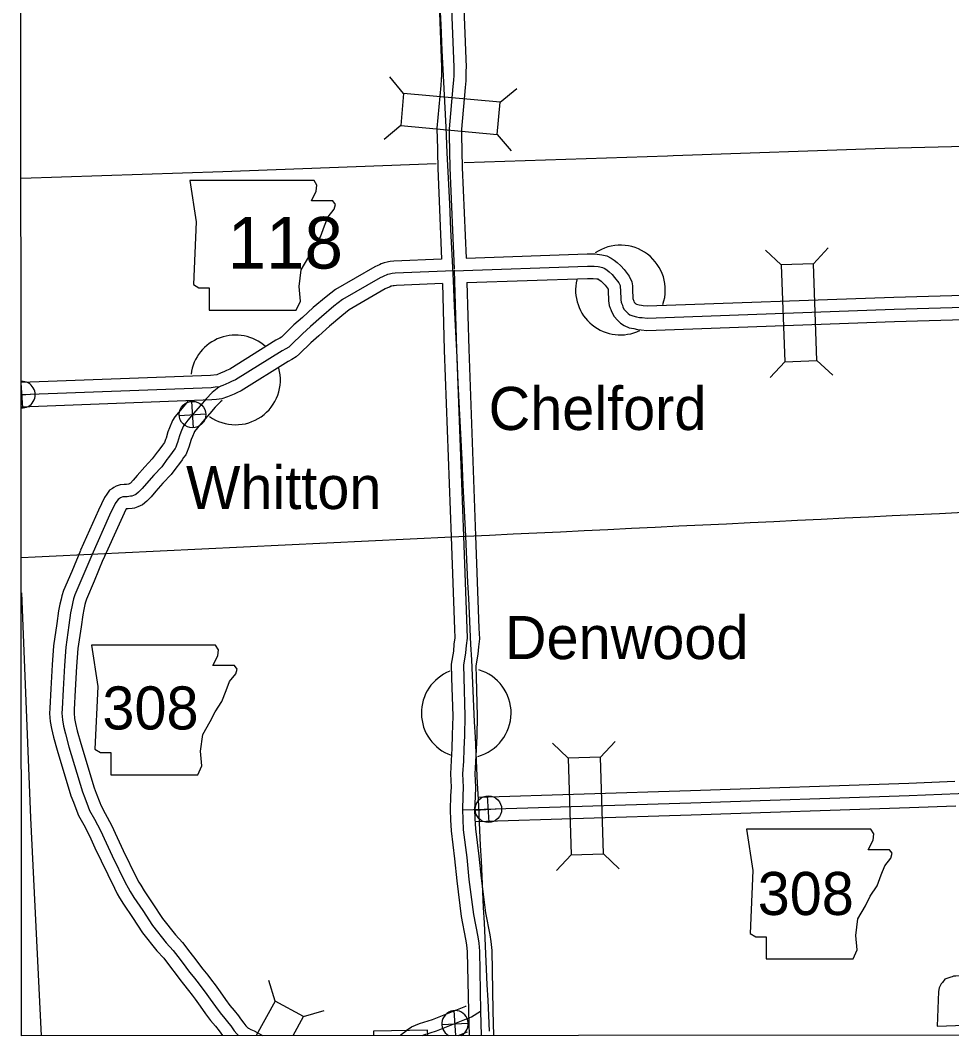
# Model space of a CAD drawing. Extents: x 2520745 to 2582119, y -1491628 to -1461664.
# Drawn here: x 2520745 to 2524549, y -1472053 to -1467904 of the extents above; entities that cross this region are included whole.
import ezdxf

# ---------------------------------------------------------------- set-up
doc = ezdxf.new("R2010")
doc.units = 0
for name, color, linetype in [('1', 7, 'Continuous'), ('10', 7, 'Continuous'), ('2', 7, 'Continuous'), ('20', 7, 'Continuous'), ('21', 7, 'Continuous'), ('24', 7, 'Continuous'), ('26', 7, 'Continuous'), ('4', 7, 'Continuous'), ('59', 7, 'Continuous'), ('6', 7, 'Continuous'), ('60', 7, 'Continuous')]:
    doc.layers.add(name, color=color, linetype=linetype)

msp = doc.modelspace()

# ---------------------------------------------------------------- linework, layer by layer
at = {"layer": '1'}
msp.add_lwpolyline([(2520744.9, -1463342.8), (2532121.5, -1463335.8), (2532126.8, -1472046.5), (2520750.2, -1472053.4)], close=True, dxfattribs=at)
at = {"layer": '10'}
for points in [[(2522449.7, -1467687), (2522465.2, -1468096.3), (2522464.9, -1468109.6), (2522465, -1468128.3), (2522464.3, -1468145.7), (2522462.1, -1468170), (2522446.4, -1468344.5), (2522446.2, -1468353.9), (2522446.5, -1468360.6), (2522447.2, -1468375.4), (2522449.9, -1468508.5), (2522465.4, -1468880.1)], [(2522549.6, -1467682.6), (2522565.3, -1468095.8), (2522564.9, -1468110.6), (2522565, -1468130), (2522564.1, -1468152.2), (2522561.8, -1468178.9), (2522546.3, -1468349.7), (2522546.3, -1468352.4), (2522546.4, -1468356.4), (2522547.1, -1468372.3), (2522549.8, -1468505.4), (2522565.4, -1468876.4)], [(2522565.4, -1468876.4), (2523060.1, -1468858.7), (2523091.7, -1468858.9), (2523110.4, -1468861.2), (2523119.5, -1468862.1), (2523140.4, -1468866.4), (2523157.7, -1468876.1), (2523170.7, -1468884.7), (2523182.7, -1468894.1), (2523197.7, -1468908.2), (2523210.6, -1468923), (2523231.5, -1468949.7), (2523242.9, -1468972.3), (2523245.3, -1468989.9), (2523245.9, -1469004.7), (2523246.9, -1469041.5), (2523251, -1469051.6), (2523252.7, -1469056.9), (2523254.8, -1469059.1), (2523259.3, -1469063.4), (2523261.4, -1469064.3), (2523273, -1469066.7), (2523281.4, -1469068.9), (2523288.3, -1469069.2), (2523306.8, -1469071.1), (2524312.7, -1469035.1), (2524973.8, -1469016.2)], [(2522465.4, -1468880.1), (2522270.9, -1468887.8), (2522255.9, -1468890.1), (2522248.7, -1468891.3), (2522242.9, -1468892.6), (2522230.4, -1468894.8), (2522219.4, -1468899.5), (2522211.3, -1468903.2), (2522205.2, -1468906), (2522192.4, -1468911), (2522032, -1469003.9), (2521994.2, -1469034), (2521941.6, -1469078.2), (2521897.3, -1469118.5), (2521862.7, -1469149.1), (2521816.1, -1469194.7), (2521811.3, -1469199.3), (2521805.5, -1469202.7), (2521789, -1469211.5), (2521600.5, -1469329.3), (2521586.4, -1469335.5), (2521576.2, -1469340.5), (2521564.7, -1469345.4), (2521547.3, -1469353.2)], [(2522568.7, -1468976.3), (2523061.6, -1468958.7), (2523085.3, -1468958.9), (2523099.4, -1468960.6), (2523104.4, -1468961.1), (2523105, -1468961.2), (2523105.5, -1468961.5), (2523112.4, -1468966), (2523117.5, -1468970.1), (2523125.5, -1468977.7), (2523133.6, -1468986.8), (2523145.8, -1469002.4), (2523146, -1469008.1), (2523147.1, -1469050.5), (2523150, -1469069.7), (2523154.6, -1469080.1), (2523156.9, -1469085.7), (2523159.8, -1469094.8), (2523170.1, -1469115.2), (2523184, -1469129.8), (2523195.9, -1469141.2), (2523210.9, -1469151.6), (2523232.2, -1469160.3), (2523250.2, -1469164.1), (2523266.1, -1469168.2), (2523280.6, -1469169), (2523303.5, -1469171.3), (2524315.9, -1469135.1), (2524976.7, -1469116.1)], [(2522468.8, -1468980.1), (2522280.7, -1468987.5), (2522271.9, -1468988.9), (2522267.9, -1468989.5), (2522262.4, -1468990.7), (2522259.1, -1468991.3), (2522252.8, -1468994.2), (2522244.4, -1468998), (2522235.7, -1469001.4), (2522088.5, -1469086.7), (2522057.5, -1469111.4), (2522007.4, -1469153.5), (2521964.1, -1469192.9), (2521930.8, -1469222.3), (2521885.6, -1469266.7), (2521871.9, -1469279.6), (2521854.3, -1469290), (2521839, -1469298.2), (2521647.2, -1469418.1), (2521628.6, -1469426.2), (2521618, -1469431.4), (2521604.7, -1469437), (2521590.8, -1469443.3), (2521567.3, -1469451.5)], [(2522468.8, -1468980.1), (2522476.3, -1469251.3)], [(2522568.7, -1468976.3), (2522576.3, -1469248.6)], [(2522476.3, -1469251.8), (2522504.4, -1470014.6), (2522518.2, -1470391.8), (2522519.6, -1470427.2), (2522516.2, -1470454), (2522513.9, -1470482.1), (2522504.9, -1470535.4), (2522506.4, -1470590.8), (2522510.9, -1470747.5), (2522509, -1470824.5), (2522506.8, -1470879.8), (2522504.5, -1470928.6), (2522501.5, -1470982.8), (2522504, -1471038), (2522502.2, -1471072.9), (2522500.2, -1471130.6), (2522501.8, -1471171.4), (2522504.5, -1471216.5), (2522518.6, -1471331.2), (2522527.4, -1471420.4), (2522546, -1471566.4), (2522563.7, -1471658.6), (2522567.5, -1471681.5), (2522570.2, -1471710.3), (2522574.9, -1471953.7)], [(2522576.2, -1469248.1), (2522604.4, -1470010.9), (2522618.2, -1470388), (2522619.8, -1470431.5), (2522615.7, -1470464.3), (2522613.2, -1470494.5), (2522605.1, -1470542.5), (2522606.3, -1470588), (2522611, -1470747.4), (2522608.9, -1470827.7), (2522606.7, -1470884.1), (2522604.4, -1470933.7), (2522601.6, -1470983.3), (2522604.1, -1471038.3), (2522602.1, -1471077.1), (2522600.3, -1471130.4), (2522601.7, -1471166.5), (2522604.1, -1471207.5), (2522618, -1471320.2), (2522626.8, -1471409.2), (2522644.8, -1471550.7), (2522662.2, -1471641), (2522666.7, -1471668.7), (2522670.1, -1471704.7), (2522674.9, -1471951.8)], [(2521547.3, -1469353.2), (2521521.3, -1469355.5), (2520748.6, -1469384.4)], [(2521567.3, -1469451.5), (2521545.7, -1469453.7), (2521527.5, -1469455.3), (2520748.6, -1469484.4)], [(2521569.2, -1469457.4), (2521562, -1469463), (2521540.7, -1469484.7), (2521518.8, -1469511.1), (2521488.7, -1469545.4), (2521468.3, -1469569.8), (2521456.5, -1469584.8), (2521454.3, -1469587.9), (2521447.5, -1469604.6), (2521443, -1469617.3), (2521433.8, -1469648.2), (2521430.1, -1469655.9), (2521426.7, -1469665.7), (2521420.7, -1469680.2), (2521411.8, -1469691.3), (2521405.5, -1469699.6), (2521390.3, -1469720.9), (2521383.9, -1469729), (2521361.2, -1469760.4), (2521327, -1469796.2), (2521298.8, -1469828.9), (2521279.7, -1469851.5), (2521261.8, -1469869.5), (2521244.4, -1469883.6), (2521225.5, -1469893), (2521211.9, -1469897.2), (2521201.1, -1469898.9), (2521184.8, -1469900.9), (2521177.8, -1469901), (2521176.3, -1469903.4), (2521154.9, -1469947.6), (2521082.1, -1470110.6)], [(2521429.7, -1469461.1), (2521412.7, -1469480.4), (2521390.7, -1469506.8), (2521376.1, -1469525.1), (2521365.8, -1469540), (2521354, -1469569), (2521347.9, -1469586.3), (2521340.4, -1469611.7), (2521337.4, -1469617.7), (2521333.6, -1469629), (2521333.2, -1469629.5), (2521325.1, -1469640), (2521310.2, -1469660.9), (2521304.1, -1469668.7), (2521284.1, -1469696.2), (2521252.9, -1469729), (2521222.8, -1469763.9), (2521206, -1469783.8), (2521194.6, -1469795.3), (2521190, -1469798.9), (2521188.6, -1469799.6), (2521187.4, -1469799.8), (2521178, -1469801), (2521168.9, -1469801.1), (2521153.3, -1469802.5), (2521136.9, -1469807.6), (2521126.9, -1469813.3), (2521121.9, -1469816.8), (2521109.8, -1469824.7), (2521097.7, -1469840.9), (2521089.1, -1469853.9), (2521064.2, -1469905.5), (2520990.8, -1470069.9)], [(2520990.3, -1470071), (2520954.8, -1470156.3), (2520920.9, -1470234.3), (2520914, -1470256.1), (2520911.3, -1470269.2), (2520906, -1470290.2), (2520900.9, -1470317.1), (2520893.9, -1470368.4), (2520880.5, -1470460.2), (2520874.9, -1470537.8), (2520869.6, -1470636.7), (2520865.6, -1470715.4), (2520864.5, -1470736.4), (2520867.1, -1470768.9), (2520872, -1470798.6), (2520880.6, -1470833.2), (2520895.7, -1470887.1), (2520951.5, -1471073.8), (2520961.7, -1471099.1), (2520975.6, -1471135.4), (2520982.5, -1471153.7), (2521003.9, -1471192.2), (2521027, -1471237.3), (2521049.9, -1471286.1), (2521074.8, -1471339.5), (2521129, -1471450.1), (2521141, -1471473.7), (2521150.5, -1471489.6), (2521165.8, -1471515.5), (2521203.1, -1471570.1), (2521244.4, -1471633.1), (2521303, -1471706), (2521330.7, -1471737.2), (2521358.5, -1471772.8), (2521381.3, -1471803.1), (2521396.3, -1471823.6), (2521411.3, -1471842.8), (2521431.6, -1471868.2), (2521446.4, -1471887.7), (2521459.7, -1471904.8), (2521478.9, -1471932.6), (2521501.5, -1471963.7), (2521521.8, -1471991.6), (2521541.8, -1472015), (2521556.8, -1472033.4), (2521563.7, -1472043), (2521571, -1472052.9)], [(2521082.6, -1470109.5), (2521046.8, -1470195.5), (2521014.7, -1470269.4), (2521010.9, -1470281.3), (2521008.8, -1470291.7), (2521003.7, -1470311.7), (2520999.7, -1470333.1), (2520992.9, -1470382.4), (2520980, -1470471), (2520974.8, -1470544.1), (2520969.5, -1470642), (2520965.5, -1470720.6), (2520964.7, -1470735.1), (2520966.5, -1470756.7), (2520970, -1470778.3), (2520977.3, -1470807.6), (2520991.8, -1470859.3), (2521046, -1471040.8), (2521054.8, -1471062.6), (2521069, -1471099.9), (2521073.4, -1471111.5), (2521092.1, -1471145), (2521116.8, -1471193.2), (2521140.5, -1471243.7), (2521165, -1471296.3), (2521218.5, -1471405.4), (2521228.7, -1471425.5), (2521236.5, -1471438.6), (2521250.2, -1471461.7), (2521286.2, -1471514.5), (2521325.4, -1471574.2), (2521379.4, -1471641.4), (2521407.6, -1471673.2), (2521437.9, -1471712), (2521461.6, -1471743.5), (2521476.1, -1471763.3), (2521489.8, -1471780.9), (2521510.5, -1471806.7), (2521525.7, -1471826.8), (2521540.5, -1471845.8), (2521560.5, -1471874.8), (2521582.4, -1471904.9), (2521600.4, -1471929.6), (2521618.6, -1471950.9), (2521636.3, -1471972.6), (2521644.5, -1471984.2), (2521657.8, -1472002.1), (2521666.6, -1472012.6), (2521675.9, -1472022.1), (2521676.2, -1472022.4), (2521677.2, -1472023.2), (2521686.1, -1472028.6), (2521699.5, -1472033.6), (2521734.6, -1472052.8)], [(2522613.1, -1471078.5), (2523482, -1471051.5), (2524373.6, -1471021.4), (2524561.8, -1471013.8)], [(2522605.7, -1471178.8), (2523485.2, -1471151.5), (2524377.3, -1471121.3), (2524565.9, -1471113.7)], [(2524736, -1471636.2), (2524677.3, -1471779.9), (2524671.2, -1471794.5), (2524662.1, -1471801.8), (2524653.3, -1471802.2), (2524636.1, -1471804.7), (2524566.2, -1471809.6), (2524556.7, -1471810.7), (2524550.6, -1471812.3), (2524544.8, -1471813.8), (2524521.2, -1471822.9), (2524511.7, -1471836.1), (2524506.6, -1471841.6), (2524498.2, -1471857.7), (2524495.2, -1471872.7), (2524489.4, -1472014.5)], [(2522321.5, -1472032.4), (2522343.2, -1472016.6), (2522375.8, -1472002.9), (2522427.8, -1471986.6), (2522564.2, -1471932.3), (2522565.9, -1471931.2)], [(2522574.9, -1471954.2), (2522577.7, -1472052.3)], [(2522674.9, -1471951.4), (2522677.7, -1472052.2)], [(2524489.4, -1472014.5), (2524940.3, -1471998.4)], [(2522296.5, -1472052.4), (2522301, -1472048.3), (2522320.2, -1472033.4)], [(2522533.1, -1472052.3), (2522570.9, -1472037.3)]]:
    msp.add_lwpolyline(points, dxfattribs=at)
at = {"layer": '2'}
msp.add_lwpolyline([(2520749.1, -1470243.7), (2520753.1, -1470311.2), (2520786.4, -1471163.4), (2520829.8, -1472053.3)], dxfattribs=at)
at = {"layer": '20'}
for p, q in [((2522310.6, -1468203), (2522254.2, -1468135.5)), ((2522704.9, -1468238.7), (2522772.5, -1468182.3)), ((2522298.7, -1468334.5), (2522231.1, -1468390.9)), ((2522693.1, -1468370.2), (2522749.4, -1468437.7)), ((2523984.6, -1468898.8), (2524044.5, -1468834.4)), ((2523852.7, -1468903.5), (2523788.3, -1468843.5)), ((2523866.8, -1469299.3), (2523806.9, -1469363.7)), ((2523998.7, -1469294.5), (2524063.2, -1469354.5)), ((2522982.9, -1470919), (2522918.7, -1470858.7)), ((2523114.8, -1470914.9), (2523175.1, -1470850.7)), ((2522995.2, -1471314.8), (2522934.9, -1471378.9)), ((2523127.1, -1471310.7), (2523191.2, -1471370.9)), ((2521785.4, -1471911.9), (2521760.6, -1471827.5)), ((2521901.3, -1471975.1), (2521985.7, -1471950.3))]:
    msp.add_line(p, q, dxfattribs=at)
for points in [[(2522704.9, -1468238.7), (2522310.6, -1468203), (2522298.7, -1468334.5), (2522693.1, -1468370.2)], [(2523852.7, -1468903.5), (2523866.8, -1469299.3), (2523998.7, -1469294.5), (2523984.6, -1468898.8)], [(2522982.9, -1470919), (2522995.2, -1471314.8), (2523127.1, -1471310.7), (2523114.8, -1470914.9)]]:
    msp.add_lwpolyline(points, close=True, dxfattribs=at)
msp.add_lwpolyline([(2521859, -1472052.7), (2521901.3, -1471975.1), (2521785.4, -1471911.9), (2521708.5, -1472052.8)], dxfattribs=at)
at = {"layer": '21'}
for points in [[(2521437.7, -1468558.2), (2521463.1, -1468727.4), (2521452, -1468984), (2521474.5, -1468998.1), (2521516.8, -1468998), (2521516.9, -1469088.3), (2521872.2, -1469088.1), (2521889.1, -1469051.4), (2521883.4, -1468992.2), (2521891.8, -1468924.5), (2521922.8, -1468870.9), (2521942.5, -1468831.5), (2521970.7, -1468789.2), (2521987.6, -1468744), (2522001.7, -1468707.4), (2522027, -1468676.3), (2522032.7, -1468656.6), (2522021.4, -1468642.5), (2521934, -1468642.6), (2521953.7, -1468603.1), (2521956.5, -1468577.7), (2521944.8, -1468558.2)], [(2521035.5, -1470457), (2521061, -1470626.1), (2521049.8, -1470882.7), (2521072.4, -1470896.8), (2521114.7, -1470896.8), (2521114.7, -1470987), (2521470, -1470986.8), (2521486.9, -1470950.2), (2521481.2, -1470891), (2521489.7, -1470823.3), (2521520.7, -1470769.7), (2521540.4, -1470730.2), (2521568.6, -1470687.9), (2521585.4, -1470642.8), (2521599.5, -1470606.1), (2521624.9, -1470575.1), (2521630.5, -1470555.4), (2521619.2, -1470541.3), (2521531.8, -1470541.3), (2521551.5, -1470501.8), (2521554.3, -1470476.4), (2521542.6, -1470457)], [(2523711.5, -1471209.5), (2523737, -1471378.7), (2523725.8, -1471635.3), (2523748.4, -1471649.4), (2523790.7, -1471649.4), (2523790.7, -1471739.6), (2524146, -1471739.4), (2524162.9, -1471702.8), (2524157.3, -1471643.6), (2524165.7, -1471575.9), (2524196.7, -1471522.3), (2524216.4, -1471482.8), (2524244.6, -1471440.5), (2524261.5, -1471395.4), (2524275.5, -1471358.7), (2524300.9, -1471327.7), (2524306.5, -1471307.9), (2524295.2, -1471293.8), (2524207.8, -1471293.9), (2524227.6, -1471254.4), (2524230.4, -1471229), (2524218.7, -1471209.5)]]:
    msp.add_lwpolyline(points, close=True, dxfattribs=at)
at = {"layer": '24'}
for centre, start, end in [((2523196, -1469006.4), 341.3465, 124.2185), ((2523196, -1469006.4), 166.8547, 295.4861), ((2521623.9, -1469373.7), 47.6753, 172.6387), ((2521623.9, -1469373.7), 234.428, 15.3416), ((2522566.2, -1470734.8), 111.4346, 250.3197), ((2522566.2, -1470734.8), 284.9058, 73.7866)]:
    msp.add_arc(centre, 183.3, start, end, dxfattribs=at)
at = {"layer": '26'}
for p, q in [((2520754.9, -1469488.2), (2520748.6, -1469386)), ((2520748.6, -1469434.4), (2520805.6, -1469430.8)), ((2521451.7, -1469569.6), (2521445, -1469461.4)), ((2521394.3, -1469518.8), (2521502.4, -1469512.2)), ((2522659.8, -1471181.9), (2522653.2, -1471073.8)), ((2522602.4, -1471131.2), (2522710.6, -1471124.5)), ((2522523.5, -1472052.3), (2522517.3, -1471950.8)), ((2522466.5, -1472008.2), (2522574.7, -1472001.6))]:
    msp.add_line(p, q, dxfattribs=at)
for centre in [(2521448.4, -1469515.5), (2522656.5, -1471127.9)]:
    msp.add_circle(centre, 54.2, dxfattribs=at)
for centre, start, end in [((2520751.6, -1469434.2), 266.9226, 93.1473), ((2522520.6, -1472004.9), 298.9855, 241.0843)]:
    msp.add_arc(centre, 54.2, start, end, dxfattribs=at)
at = {"layer": '4'}
for points in [[(2526235.8, -1468369.3), (2526028.1, -1468377.4), (2525166, -1468406.9), (2525148, -1468405.7), (2524276.2, -1468427.9), (2523411.1, -1468458.6), (2523388.2, -1468459.5), (2522558.3, -1468486.6)], [(2522443.6, -1468490.6), (2521572.7, -1468523), (2520748.1, -1468551)]]:
    msp.add_lwpolyline(points, dxfattribs=at)
at = {"layer": '59'}
for points in [[(2522499.7, -1467684.8), (2522515.3, -1468096), (2522514.9, -1468110.1), (2522515, -1468129.2), (2522514.2, -1468148.9), (2522511.9, -1468174.5), (2522496.3, -1468347.1), (2522496.3, -1468353.1), (2522496.5, -1468358.5), (2522497.1, -1468373.9), (2522499.8, -1468506.9), (2522517.2, -1468921.1)], [(2522515.2, -1468928.2), (2523060.8, -1468908.7), (2523088.5, -1468908.9), (2523104.9, -1468910.9), (2523111.9, -1468911.6), (2523122.7, -1468913.8), (2523131.6, -1468918.8), (2523141.5, -1468925.4), (2523150.1, -1468932.1), (2523161.6, -1468942.9), (2523172.1, -1468954.9), (2523189, -1468976.6), (2523194.5, -1468987.4), (2523195.5, -1468994.4), (2523196, -1469006.4), (2523197, -1469046.2), (2523198.4, -1469055.5), (2523200.6, -1469060.4), (2523204, -1469068.6), (2523206.3, -1469075.9), (2523211.4, -1469086), (2523219.4, -1469094.4), (2523227.7, -1469102.4), (2523234.9, -1469107.5), (2523246.8, -1469112.3), (2523261.6, -1469115.4), (2523273.7, -1469118.5), (2523284.4, -1469119.1), (2523305.2, -1469121.2), (2524314.3, -1469085.1), (2524975.3, -1469066.1)], [(2522515.2, -1468928.2), (2523060.8, -1468908.7), (2523088.5, -1468908.9), (2523104.9, -1468910.9), (2523111.9, -1468911.6), (2523122.7, -1468913.8), (2523131.6, -1468918.8), (2523141.5, -1468925.4), (2523150.1, -1468932.1), (2523161.6, -1468942.9), (2523172.1, -1468954.9), (2523189, -1468976.6), (2523194.5, -1468987.4), (2523195.5, -1468994.4), (2523196, -1469006.4), (2523197, -1469046.2), (2523198.4, -1469055.5), (2523200.6, -1469060.4), (2523204, -1469068.6), (2523206.3, -1469075.9), (2523211.4, -1469086), (2523219.4, -1469094.4), (2523227.7, -1469102.4), (2523234.9, -1469107.5), (2523246.8, -1469112.3), (2523261.6, -1469115.4), (2523273.7, -1469118.5), (2523284.4, -1469119.1), (2523305.2, -1469121.2), (2524314.3, -1469085.1), (2524975.3, -1469066.1)], [(2522515.2, -1468928.2), (2522275.8, -1468937.6), (2522263.9, -1468939.5), (2522258.3, -1468940.4), (2522252.7, -1468941.7), (2522244.8, -1468943.1), (2522239.5, -1468945.3), (2522232, -1468948.7), (2522224.8, -1468952), (2522214, -1468956.2), (2522060.2, -1469045.3), (2522025.8, -1469072.7), (2521974.5, -1469115.9), (2521930.7, -1469155.7), (2521896.8, -1469185.7), (2521850.8, -1469230.7), (2521841.6, -1469239.5), (2521829.9, -1469246.4), (2521814, -1469254.8), (2521623.9, -1469373.7), (2521607.5, -1469380.8), (2521597.1, -1469386), (2521584.7, -1469391.2), (2521572.3, -1469396.8), (2521563.4, -1469399.9), (2521558.5, -1469402.1), (2521556.3, -1469403.9)], [(2522517.3, -1468925.5), (2522526.3, -1469249.9)], [(2522517.3, -1468925.5), (2522526.3, -1469249.9)], [(2522526.3, -1469249.9), (2522554.4, -1470012.7), (2522568.2, -1470389.9), (2522569.7, -1470429.3), (2522566, -1470459.2), (2522563.6, -1470488.3), (2522555, -1470539), (2522556.4, -1470589.4), (2522561, -1470747.5), (2522558.9, -1470826.1), (2522556.8, -1470882), (2522554.5, -1470931.2), (2522551.5, -1470983), (2522554, -1471038.2), (2522552.1, -1471075), (2522550.3, -1471130.5), (2522551.7, -1471168.9), (2522554.3, -1471212), (2522568.3, -1471325.7), (2522577.1, -1471414.8), (2522595.4, -1471558.5), (2522612.9, -1471649.8), (2522617.1, -1471675.1), (2522620.1, -1471707.5), (2522624.9, -1471952.8)], [(2522526.3, -1469249.9), (2522554.4, -1470012.7), (2522568.2, -1470389.9), (2522569.7, -1470429.3), (2522566, -1470459.2), (2522563.6, -1470488.3), (2522555, -1470539), (2522556.4, -1470589.4), (2522561, -1470747.5), (2522558.9, -1470826.1), (2522556.8, -1470882), (2522554.5, -1470931.2), (2522551.5, -1470983), (2522554, -1471038.2), (2522552.1, -1471075), (2522550.3, -1471130.5), (2522551.7, -1471168.9), (2522554.3, -1471212), (2522568.3, -1471325.7), (2522577.1, -1471414.8), (2522595.4, -1471558.5), (2522612.9, -1471649.8), (2522617.1, -1471675.1), (2522620.1, -1471707.5), (2522624.9, -1471952.8)], [(2521558.5, -1469402.1), (2521541, -1469404), (2521524.4, -1469405.4), (2520748.6, -1469434.4)], [(2521556.3, -1469403.9), (2521528.6, -1469425.6), (2521503.5, -1469451.2), (2521480.8, -1469478.7), (2521450.7, -1469512.9), (2521429.5, -1469538.3), (2521416.3, -1469555), (2521410.1, -1469564), (2521400.8, -1469586.8), (2521395.5, -1469601.8), (2521387.1, -1469629.9), (2521383.8, -1469636.8), (2521379.9, -1469648), (2521377.2, -1469654.5), (2521372.5, -1469660.4), (2521365.3, -1469669.8), (2521350.3, -1469690.9), (2521344, -1469698.9), (2521322.7, -1469728.3), (2521289.9, -1469762.6), (2521260.8, -1469796.4), (2521242.8, -1469817.7), (2521228.2, -1469832.4), (2521217.2, -1469841.3), (2521206.8, -1469846.4), (2521200.6, -1469848.4), (2521194.3, -1469849.4), (2521181.4, -1469851), (2521171.4, -1469851.1), (2521163.1, -1469851.8), (2521156.8, -1469853.8), (2521153.6, -1469855.6), (2521150, -1469858.1), (2521144.6, -1469861.7), (2521138.6, -1469869.7), (2521132.7, -1469878.6), (2521109.6, -1469926.6), (2521036.5, -1470090.3)], [(2521036.5, -1470090.3), (2521000.8, -1470175.9), (2520967.8, -1470251.8), (2520962.5, -1470268.7), (2520960, -1470280.4), (2520954.8, -1470300.9), (2520950.3, -1470325.1), (2520943.4, -1470375.4), (2520930.3, -1470465.6), (2520924.8, -1470540.9), (2520919.6, -1470639.4), (2520915.5, -1470718), (2520914.6, -1470735.8), (2520916.8, -1470762.8), (2520921, -1470788.4), (2520929, -1470820.4), (2520943.7, -1470873.2), (2520998.8, -1471057.3), (2521008.2, -1471080.8), (2521022.3, -1471117.7), (2521027.9, -1471132.6), (2521048, -1471168.6), (2521071.9, -1471215.3), (2521095.2, -1471264.9), (2521119.9, -1471317.9), (2521173.8, -1471427.8), (2521184.9, -1471449.6), (2521193.5, -1471464.1), (2521208, -1471488.6), (2521244.7, -1471542.3), (2521284.9, -1471603.7), (2521341.2, -1471673.7), (2521369.2, -1471705.2), (2521398.2, -1471742.4), (2521421.5, -1471773.3), (2521436.2, -1471793.4), (2521450.6, -1471811.8), (2521471, -1471837.5), (2521486.1, -1471857.2), (2521500.1, -1471875.3), (2521519.7, -1471903.7), (2521541.9, -1471934.3), (2521561.1, -1471960.6), (2521580.2, -1471983), (2521596.6, -1472003), (2521604.1, -1472013.6), (2521618.5, -1472033), (2521629.4, -1472046.1), (2521636, -1472052.8)], [(2522550.3, -1471130.5), (2523483.6, -1471101.5), (2524375.5, -1471071.4), (2525042.2, -1471044.3), (2525064.2, -1471042.9), (2525073.2, -1471043.1)], [(2522387.1, -1472052.4), (2522393, -1472049.9), (2522444.6, -1472033.8), (2522587.1, -1471977), (2522624.9, -1471952.8)], [(2522624.9, -1471952.8), (2522627.7, -1472052.2)], [(2522624.9, -1471952.8), (2522627.7, -1472052.2)]]:
    msp.add_lwpolyline(points, dxfattribs=at)
at = {"layer": '6'}
for points in [[(2522409.1, -1472052.4), (2522408.4, -1472030.7), (2522187.4, -1472034.6)], [(2522187.4, -1472034.6), (2522188.1, -1472052.5)]]:
    msp.add_lwpolyline(points, dxfattribs=at)
at = {"layer": '60'}
for points in [[(2522661.4, -1472034.5), (2522564.1, -1470012.5), (2522241.7, -1463325.1)], [(2520749.1, -1470099.6), (2522564.1, -1470012.5), (2528758.3, -1469710.2), (2532125.3, -1469542.5)]]:
    msp.add_spline(points, degree=3, dxfattribs=at)

# ---------------------------------------------------------------- texts
at = {"layer": '21'}
for s, height, p in [('118', 211.2, (2521591.5, -1468918.8)), ('308', 176, (2521080.2, -1470802.1)), ('308', 176, (2523756.6, -1471560.3))]:
    msp.add_text(s, height=height, dxfattribs=at).set_placement(p)
at = {"layer": '24'}
for s, p in [('Chelford', (2522657.5, -1469578.4)), ('Whitton', (2521421.8, -1469901.5)), ('Denwood', (2522724.2, -1470514.6))]:
    msp.add_text(s, height=176, dxfattribs=at).set_placement(p)

doc.saveas('drawing.dxf')
